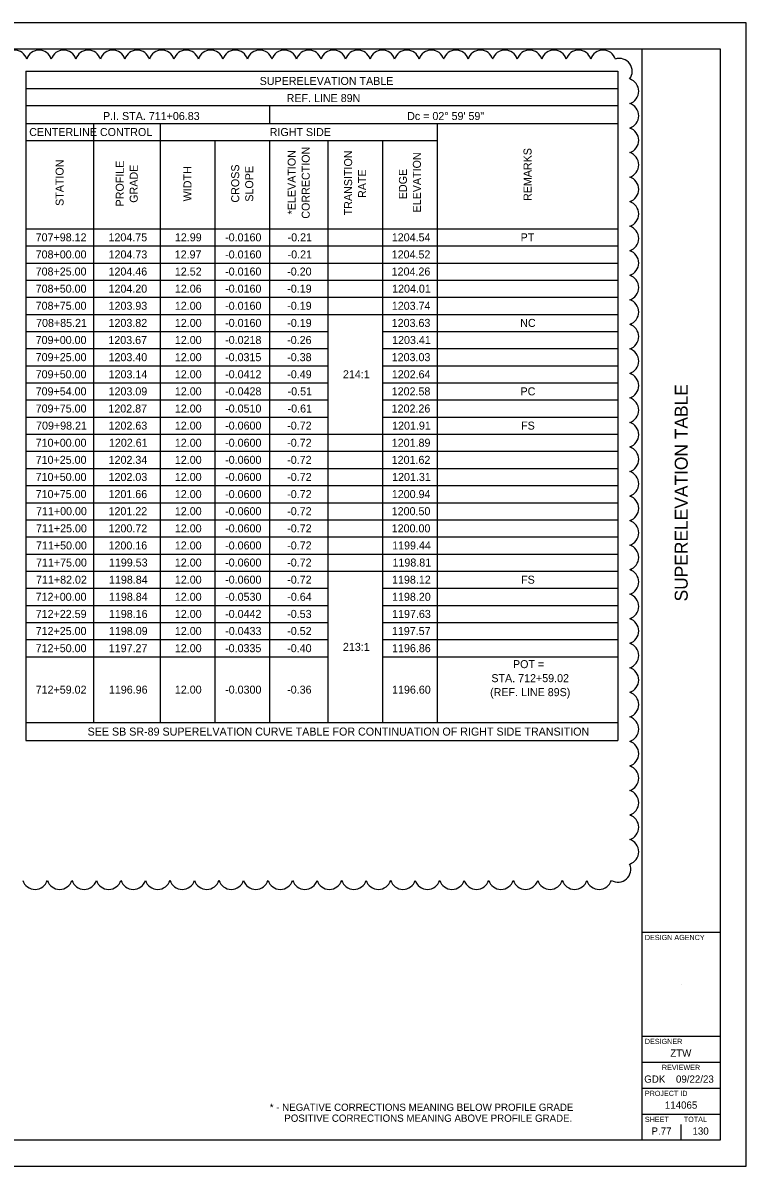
# Model space of a CAD drawing. Extents: x 0 to 34, y 0 to 22.
# Drawn here: x 20.07 to 34, y 0 to 22 of the extents above; entities that cross this region are included whole.
import ezdxf

# ---------------------------------------------------------------- set-up
doc = ezdxf.new("R2010")
doc.units = 0
for name, color, linetype in [('MU_Markup_Cloud', 7, 'Continuous'), ('SH_Border', 7, 'Continuous'), ('SH_Cut_Line', 7, 'Continuous'), ('SH_Data', 7, 'Continuous'), ('SH_Text', 7, 'Continuous')]:
    doc.layers.add(name, color=color, linetype=linetype)

msp = doc.modelspace()

# ---------------------------------------------------------------- linework, layer by layer
at = {"layer": 'MU_Markup_Cloud'}
for centre, radius, start, end in [((19.914, 21.228), 0.248, 17.5, 162.5), ((20.386, 21.228), 0.247, 17.5, 162.5), ((20.859, 21.228), 0.248, 17.5, 162.5), ((21.331, 21.228), 0.248, 17.5, 162.5), ((21.803, 21.228), 0.248, 17.5, 162.5), ((22.275, 21.228), 0.248, 17.5, 162.5), ((22.747, 21.228), 0.248, 17.5, 162.5), ((23.219, 21.228), 0.248, 17.5, 162.5), ((23.691, 21.228), 0.248, 17.5, 162.5), ((24.163, 21.228), 0.248, 17.5, 162.5), ((24.635, 21.228), 0.248, 17.5, 162.5), ((25.107, 21.228), 0.248, 17.5, 162.5), ((25.58, 21.228), 0.248, 17.5, 162.5), ((26.052, 21.228), 0.248, 17.5, 162.5), ((26.524, 21.228), 0.248, 17.5, 162.5), ((26.996, 21.228), 0.248, 17.5, 162.5), ((27.468, 21.228), 0.248, 17.5, 162.5), ((27.94, 21.228), 0.248, 17.5, 162.5), ((28.412, 21.228), 0.248, 17.5, 162.5), ((28.884, 21.228), 0.248, 17.5, 162.5), ((29.356, 21.228), 0.248, 17.5, 162.5), ((29.829, 21.228), 0.248, 17.5, 162.5), ((30.301, 21.228), 0.248, 17.5, 162.5), ((30.773, 21.228), 0.248, 17.5, 162.5), ((31.245, 21.228), 0.248, 17.5, 162.5), ((31.559, 21.068), 0.247, 323.3825, 108.3825), ((31.683, 20.684), 0.248, 287.5, 72.5), ((31.683, 20.212), 0.248, 287.5, 72.5), ((31.683, 19.74), 0.248, 287.5, 72.5), ((31.683, 19.268), 0.248, 287.5, 72.5), ((31.683, 18.796), 0.248, 287.5, 72.5), ((31.683, 18.323), 0.248, 287.5, 72.5), ((31.683, 17.851), 0.248, 287.5, 72.5), ((31.683, 17.379), 0.248, 287.5, 72.5), ((31.683, 16.907), 0.248, 287.5, 72.5), ((31.683, 16.435), 0.248, 287.5, 72.5), ((31.683, 15.963), 0.248, 287.5, 72.5), ((31.683, 15.491), 0.248, 287.5, 72.5), ((31.683, 15.019), 0.248, 287.5, 72.5), ((31.683, 14.547), 0.248, 287.5, 72.5), ((31.683, 14.075), 0.248, 287.5, 72.5), ((31.683, 13.602), 0.248, 287.5, 72.5), ((31.683, 13.13), 0.248, 287.5, 72.5), ((31.683, 12.658), 0.248, 287.5, 72.5), ((31.683, 12.186), 0.248, 287.5, 72.5), ((31.683, 11.714), 0.248, 287.5, 72.5), ((31.683, 11.242), 0.248, 287.5, 72.5), ((31.683, 10.77), 0.248, 287.5, 72.5), ((31.683, 10.298), 0.248, 287.5, 72.5), ((31.683, 9.826), 0.248, 287.5, 72.5), ((31.683, 9.354), 0.248, 287.5, 72.5), ((31.683, 8.881), 0.248, 287.5, 72.5), ((31.683, 8.409), 0.248, 287.5, 72.5), ((31.683, 7.937), 0.248, 287.5, 72.5), ((31.683, 7.465), 0.248, 287.5, 72.5), ((31.683, 6.993), 0.248, 287.5, 72.5), ((31.683, 6.521), 0.248, 287.5, 72.5), ((31.683, 6.049), 0.248, 287.5, 72.5), ((31.532, 5.711), 0.247, 239.1824, 24.1824), ((20.31, 5.573), 0.248, 197.5, 342.5), ((20.783, 5.573), 0.248, 197.5, 342.5), ((21.255, 5.573), 0.248, 197.5, 342.5), ((21.727, 5.573), 0.248, 197.5, 342.5), ((22.199, 5.573), 0.248, 197.5, 342.5), ((22.671, 5.573), 0.248, 197.5, 342.5), ((23.143, 5.573), 0.248, 197.5, 342.5), ((23.615, 5.573), 0.248, 197.5, 342.5), ((24.087, 5.573), 0.248, 197.5, 342.5), ((24.559, 5.573), 0.248, 197.5, 342.5), ((25.031, 5.573), 0.248, 197.5, 342.5), ((25.504, 5.573), 0.248, 197.5, 342.5), ((25.976, 5.573), 0.248, 197.5, 342.5), ((26.448, 5.573), 0.248, 197.5, 342.5), ((26.92, 5.573), 0.248, 197.5, 342.5), ((27.392, 5.573), 0.248, 197.5, 342.5), ((27.864, 5.573), 0.248, 197.5, 342.5), ((28.336, 5.573), 0.248, 197.5, 342.5), ((28.808, 5.573), 0.248, 197.5, 342.5), ((29.28, 5.573), 0.248, 197.5, 342.5), ((29.752, 5.573), 0.248, 197.5, 342.5), ((30.225, 5.573), 0.248, 197.5, 342.5), ((30.697, 5.573), 0.248, 197.5, 342.5), ((31.169, 5.573), 0.248, 197.5, 342.5)]:
    msp.add_arc(centre, radius, start, end, dxfattribs=at)
at = {"layer": 'SH_Border'}
for p, q in [((32, 0.5), (32, 21.5)), ((32, 4.5), (33.5, 4.5)), ((32, 2.5), (33.5, 2.5)), ((32, 2), (33.5, 2)), ((32, 1.5), (33.5, 1.5)), ((32, 1), (33.5, 1))]:
    msp.add_line(p, q, dxfattribs=at)
msp.add_lwpolyline([(1.5, 21.5), (33.5, 21.5), (33.5, 0.5), (1.5, 0.5)], close=True, dxfattribs=at)
at = {"layer": 'SH_Cut_Line'}
msp.add_lwpolyline([(0, 0), (34, 0), (34, 22), (0, 22)], close=True, dxfattribs=at)
at = {"layer": 'SH_Data'}
for p, q in [((32.75, 3.5), (32.75, 3.5)), ((32.375, 0.675), (32.375, 0.675)), ((32.75, 0.5), (32.75, 0.8))]:
    msp.add_line(p, q, dxfattribs=at)
at = {"layer": 'SH_Text'}
for p, q in [((20.131, 21.069), (31.529, 21.069)), ((20.131, 21.069), (20.131, 8.189)), ((31.529, 21.069), (31.529, 8.189)), ((20.131, 20.739), (31.529, 20.739)), ((20.131, 20.41), (31.529, 20.41)), ((24.825, 20.41), (24.825, 20.064)), ((20.131, 20.064), (31.529, 20.064)), ((21.432, 20.064), (21.432, 8.535)), ((22.717, 20.064), (22.717, 8.535)), ((28.053, 20.064), (28.053, 8.535)), ((20.131, 19.735), (28.053, 19.735)), ((23.771, 19.735), (23.771, 8.535)), ((24.825, 19.735), (24.825, 8.535)), ((25.945, 19.735), (25.945, 8.535)), ((26.999, 19.735), (26.999, 8.535)), ((20.131, 18.038), (31.529, 18.038)), ((20.131, 17.709), (31.529, 17.709)), ((20.131, 17.379), (31.529, 17.379)), ((20.131, 17.05), (31.529, 17.05)), ((20.131, 16.72), (31.529, 16.72)), ((20.131, 16.391), (31.529, 16.391)), ((20.131, 16.062), (25.945, 16.062)), ((26.999, 16.062), (31.529, 16.062)), ((20.131, 15.732), (25.945, 15.732)), ((26.999, 15.732), (31.529, 15.732)), ((20.131, 15.403), (25.945, 15.403)), ((26.999, 15.403), (31.529, 15.403)), ((20.131, 15.073), (25.945, 15.073)), ((26.999, 15.073), (31.529, 15.073)), ((20.131, 14.744), (25.945, 14.744)), ((26.999, 14.744), (31.529, 14.744)), ((20.131, 14.415), (25.945, 14.415)), ((26.999, 14.415), (31.529, 14.415)), ((20.131, 14.085), (31.529, 14.085)), ((20.131, 13.756), (31.529, 13.756)), ((20.131, 13.426), (31.529, 13.426)), ((20.131, 13.097), (31.529, 13.097)), ((20.131, 12.767), (31.529, 12.767)), ((20.131, 12.438), (31.529, 12.438)), ((20.131, 12.109), (31.529, 12.109)), ((20.131, 11.779), (31.529, 11.779)), ((20.131, 11.45), (31.529, 11.45)), ((20.131, 11.12), (25.945, 11.12)), ((26.999, 11.12), (31.529, 11.12)), ((20.131, 10.791), (25.945, 10.791)), ((26.999, 10.791), (31.529, 10.791)), ((20.131, 10.462), (25.945, 10.462)), ((26.999, 10.462), (31.529, 10.462)), ((20.131, 10.132), (25.945, 10.132)), ((26.999, 10.132), (31.529, 10.132)), ((20.131, 9.803), (25.945, 9.803)), ((26.999, 9.803), (31.529, 9.803)), ((20.131, 8.535), (28.053, 8.535)), ((28.053, 8.535), (31.529, 8.535)), ((20.131, 8.189), (31.529, 8.189))]:
    msp.add_line(p, q, dxfattribs=at)

# ---------------------------------------------------------------- texts
at = {"layer": 'SH_Data'}
msp.add_text('SUPERELEVATION TABLE', height=0.25, rotation=90, dxfattribs=at).set_placement((32.875, 10.867))
for s, height, p in [('DESIGN AGENCY', 0.1, (32.05, 4.35)), ('DESIGNER', 0.1, (32.05, 2.35)), ('ZTW', 0.14, (32.539, 2.105)), ('REVIEWER', 0.1, (32.378, 1.85)), ('GDK', 0.14, (32.038, 1.605)), ('09/22/23', 0.14, (32.649, 1.605)), ('PROJECT ID', 0.1, (32.05, 1.35)), ('114065', 0.14, (32.435, 1.105)), ('SHEET', 0.1, (32.05, 0.85)), ('TOTAL', 0.1, (32.8, 0.85)), ('P.77', 0.14, (32.178, 0.605)), ('130', 0.14, (32.967, 0.605))]:
    msp.add_text(s, height=height, dxfattribs=at).set_placement(p)
at = {"layer": 'SH_Text'}
for s, height, p in [('SUPERELEVATION TABLE', 0.154, (24.634, 20.805)), ('REF. LINE 89N', 0.154, (25.153, 20.476)), ('P.I. STA. 711+06.83', 0.154, (21.618, 20.13)), ('Dc = 02° 59\' 59"', 0.154, (27.473, 20.13)), ('CENTERLINE CONTROL', 0.154, (20.197, 19.822)), ('RIGHT SIDE', 0.154, (24.827, 19.822)), ('707+98.12', 0.154, (20.321, 17.796)), ('1204.75', 0.154, (21.723, 17.796)), ('12.99', 0.154, (23.002, 17.796)), ('-0.0160', 0.154, (23.969, 17.796)), ('-0.21', 0.154, (25.172, 17.796)), ('1204.54', 0.154, (27.178, 17.796)), ('PT', 0.154, (29.658, 17.796)), ('708+00.00', 0.154, (20.321, 17.467)), ('1204.73', 0.154, (21.725, 17.467)), ('12.97', 0.154, (22.998, 17.467)), ('-0.0160', 0.154, (23.969, 17.467)), ('-0.21', 0.154, (25.172, 17.467)), ('1204.52', 0.154, (27.176, 17.467)), ('708+25.00', 0.154, (20.321, 17.138)), ('1204.46', 0.154, (21.724, 17.138)), ('12.52', 0.154, (23.001, 17.138)), ('-0.0160', 0.154, (23.969, 17.138)), ('-0.20', 0.154, (25.164, 17.138)), ('1204.26', 0.154, (27.175, 17.138)), ('708+50.00', 0.154, (20.321, 16.808)), ('1204.20', 0.154, (21.724, 16.808)), ('12.06', 0.154, (23.001, 16.808)), ('-0.0160', 0.154, (23.969, 16.808)), ('-0.19', 0.154, (25.165, 16.808)), ('1204.01', 0.154, (27.184, 16.808)), ('708+75.00', 0.154, (20.321, 16.479)), ('1203.93', 0.154, (21.725, 16.479)), ('12.00', 0.154, (23.001, 16.479)), ('-0.0160', 0.154, (23.969, 16.479)), ('-0.19', 0.154, (25.165, 16.479)), ('1203.74', 0.154, (27.178, 16.479)), ('708+85.21', 0.154, (20.329, 16.149)), ('1203.82', 0.154, (21.724, 16.149)), ('12.00', 0.154, (23.001, 16.149)), ('-0.0160', 0.154, (23.969, 16.149)), ('-0.19', 0.154, (25.165, 16.149)), ('1203.63', 0.154, (27.176, 16.149)), ('NC', 0.154, (29.65, 16.149)), ('709+00.00', 0.154, (20.321, 15.82)), ('1203.67', 0.154, (21.721, 15.82)), ('12.00', 0.154, (23.001, 15.82)), ('-0.0218', 0.154, (23.969, 15.82)), ('-0.26', 0.154, (25.163, 15.82)), ('1203.41', 0.154, (27.184, 15.82)), ('709+25.00', 0.154, (20.321, 15.49)), ('1203.40', 0.154, (21.724, 15.49)), ('12.00', 0.154, (23.001, 15.49)), ('-0.0315', 0.154, (23.968, 15.49)), ('-0.38', 0.154, (25.164, 15.49)), ('1203.03', 0.154, (27.176, 15.49)), ('709+50.00', 0.154, (20.321, 15.161)), ('1203.14', 0.154, (21.726, 15.161)), ('12.00', 0.154, (23.001, 15.161)), ('-0.0412', 0.154, (23.969, 15.161)), ('-0.49', 0.154, (25.165, 15.161)), ('214:1', 0.154, (26.237, 15.161)), ('1202.64', 0.154, (27.178, 15.161)), ('709+54.00', 0.154, (20.321, 14.832)), ('1203.09', 0.154, (21.725, 14.832)), ('12.00', 0.154, (23.001, 14.832)), ('-0.0428', 0.154, (23.969, 14.832)), ('-0.51', 0.154, (25.172, 14.832)), ('1202.58', 0.154, (27.176, 14.832)), ('PC', 0.154, (29.656, 14.832)), ('709+75.00', 0.154, (20.321, 14.502)), ('1202.87', 0.154, (21.721, 14.502)), ('12.00', 0.154, (23.001, 14.502)), ('-0.0510', 0.154, (23.969, 14.502)), ('-0.61', 0.154, (25.172, 14.502)), ('1202.26', 0.154, (27.175, 14.502)), ('709+98.21', 0.154, (20.329, 14.173)), ('1202.63', 0.154, (21.725, 14.173)), ('12.00', 0.154, (23.001, 14.173)), ('-0.0600', 0.154, (23.969, 14.173)), ('-0.72', 0.154, (25.164, 14.173)), ('1201.91', 0.154, (27.184, 14.173)), ('FS', 0.154, (29.667, 14.173)), ('710+00.00', 0.154, (20.321, 13.843)), ('1202.61', 0.154, (21.732, 13.843)), ('12.00', 0.154, (23.001, 13.843)), ('-0.0600', 0.154, (23.969, 13.843)), ('-0.72', 0.154, (25.164, 13.843)), ('1201.89', 0.154, (27.177, 13.843)), ('710+25.00', 0.154, (20.321, 13.514)), ('1202.34', 0.154, (21.726, 13.514)), ('12.00', 0.154, (23.001, 13.514)), ('-0.0600', 0.154, (23.969, 13.514)), ('-0.72', 0.154, (25.164, 13.514)), ('1201.62', 0.154, (27.176, 13.514)), ('710+50.00', 0.154, (20.321, 13.185)), ('1202.03', 0.154, (21.725, 13.185)), ('12.00', 0.154, (23.001, 13.185)), ('-0.0600', 0.154, (23.969, 13.185)), ('-0.72', 0.154, (25.164, 13.185)), ('1201.31', 0.154, (27.184, 13.185)), ('710+75.00', 0.154, (20.321, 12.855)), ('1201.66', 0.154, (21.724, 12.855)), ('12.00', 0.154, (23.001, 12.855)), ('-0.0600', 0.154, (23.969, 12.855)), ('-0.72', 0.154, (25.164, 12.855)), ('1200.94', 0.154, (27.178, 12.855)), ('711+00.00', 0.154, (20.328, 12.526)), ('1201.22', 0.154, (21.724, 12.526)), ('12.00', 0.154, (23.001, 12.526)), ('-0.0600', 0.154, (23.969, 12.526)), ('-0.72', 0.154, (25.164, 12.526)), ('1200.50', 0.154, (27.176, 12.526)), ('711+25.00', 0.154, (20.328, 12.196)), ('1200.72', 0.154, (21.724, 12.196)), ('12.00', 0.154, (23.001, 12.196)), ('-0.0600', 0.154, (23.969, 12.196)), ('-0.72', 0.154, (25.164, 12.196)), ('1200.00', 0.154, (27.176, 12.196)), ('711+50.00', 0.154, (20.328, 11.867)), ('1200.16', 0.154, (21.724, 11.867)), ('12.00', 0.154, (23.001, 11.867)), ('-0.0600', 0.154, (23.969, 11.867)), ('-0.72', 0.154, (25.164, 11.867)), ('1199.44', 0.154, (27.185, 11.867)), ('711+75.00', 0.154, (20.328, 11.538)), ('1199.53', 0.154, (21.732, 11.538)), ('12.00', 0.154, (23.001, 11.538)), ('-0.0600', 0.154, (23.969, 11.538)), ('-0.72', 0.154, (25.164, 11.538)), ('1198.81', 0.154, (27.191, 11.538)), ('711+82.02', 0.154, (20.328, 11.208)), ('1198.84', 0.154, (21.733, 11.208)), ('12.00', 0.154, (23.001, 11.208)), ('-0.0600', 0.154, (23.969, 11.208)), ('-0.72', 0.154, (25.164, 11.208)), ('1198.12', 0.154, (27.183, 11.208)), ('FS', 0.154, (29.667, 11.208)), ('712+00.00', 0.154, (20.321, 10.879)), ('1198.84', 0.154, (21.733, 10.879)), ('12.00', 0.154, (23.001, 10.879)), ('-0.0530', 0.154, (23.969, 10.879)), ('-0.64', 0.154, (25.166, 10.879)), ('1198.20', 0.154, (27.183, 10.879)), ('712+22.59', 0.154, (20.322, 10.549)), ('1198.16', 0.154, (21.731, 10.549)), ('12.00', 0.154, (23.001, 10.549)), ('-0.0442', 0.154, (23.969, 10.549)), ('-0.53', 0.154, (25.164, 10.549)), ('1197.63', 0.154, (27.184, 10.549)), ('712+25.00', 0.154, (20.321, 10.22)), ('1198.09', 0.154, (21.732, 10.22)), ('12.00', 0.154, (23.001, 10.22)), ('-0.0433', 0.154, (23.97, 10.22)), ('-0.52', 0.154, (25.164, 10.22)), ('1197.57', 0.154, (27.18, 10.22)), ('712+50.00', 0.154, (20.321, 9.89)), ('1197.27', 0.154, (21.728, 9.89)), ('12.00', 0.154, (23.001, 9.89)), ('-0.0335', 0.154, (23.968, 9.89)), ('-0.40', 0.154, (25.164, 9.89)), ('213:1', 0.154, (26.237, 9.915)), ('1196.86', 0.154, (27.183, 9.89)), ('POT = ', 0.154, (29.511, 9.583)), ('STA. 712+59.02', 0.154, (29.095, 9.313)), ('712+59.02', 0.154, (20.321, 9.092)), ('1196.96', 0.154, (21.731, 9.092)), ('12.00', 0.154, (23.001, 9.092)), ('-0.0300', 0.154, (23.969, 9.092)), ('-0.36', 0.154, (25.163, 9.092)), ('1196.60', 0.154, (27.183, 9.092)), ('(REF. LINE 89S)', 0.154, (29.07, 9.044)), ('SEE SB SR-89 SUPERELVATION CURVE TABLE FOR CONTINUATION OF RIGHT SIDE TRANSITION', 0.154, (21.321, 8.285)), ('* - NEGATIVE CORRECTIONS MEANING BELOW PROFILE GRADE', 0.14, (24.828, 1.063)), ('POSITIVE CORRECTIONS MEANING ABOVE PROFILE GRADE.', 0.14, (25.108, 0.853))]:
    msp.add_text(s, height=height, dxfattribs=at).set_placement(p)
for s, p in [('CORRECTION', (25.597, 18.232)), ('REMARKS', (29.868, 18.572)), ('*ELEVATION ', (25.327, 18.315)), ('TRANSITION ', (26.414, 18.297)), ('ELEVATION', (27.738, 18.352)), ('STATION', (20.859, 18.478)), ('PROFILE ', (22.017, 18.468)), ('GRADE', (22.286, 18.538)), ('WIDTH', (23.321, 18.566)), ('CROSS ', (24.24, 18.542)), ('SLOPE', (24.51, 18.559)), ('RATE', (26.684, 18.631)), ('EDGE ', (27.469, 18.607))]:
    msp.add_text(s, height=0.154, rotation=90, dxfattribs=at).set_placement(p)

doc.saveas('drawing.dxf')
